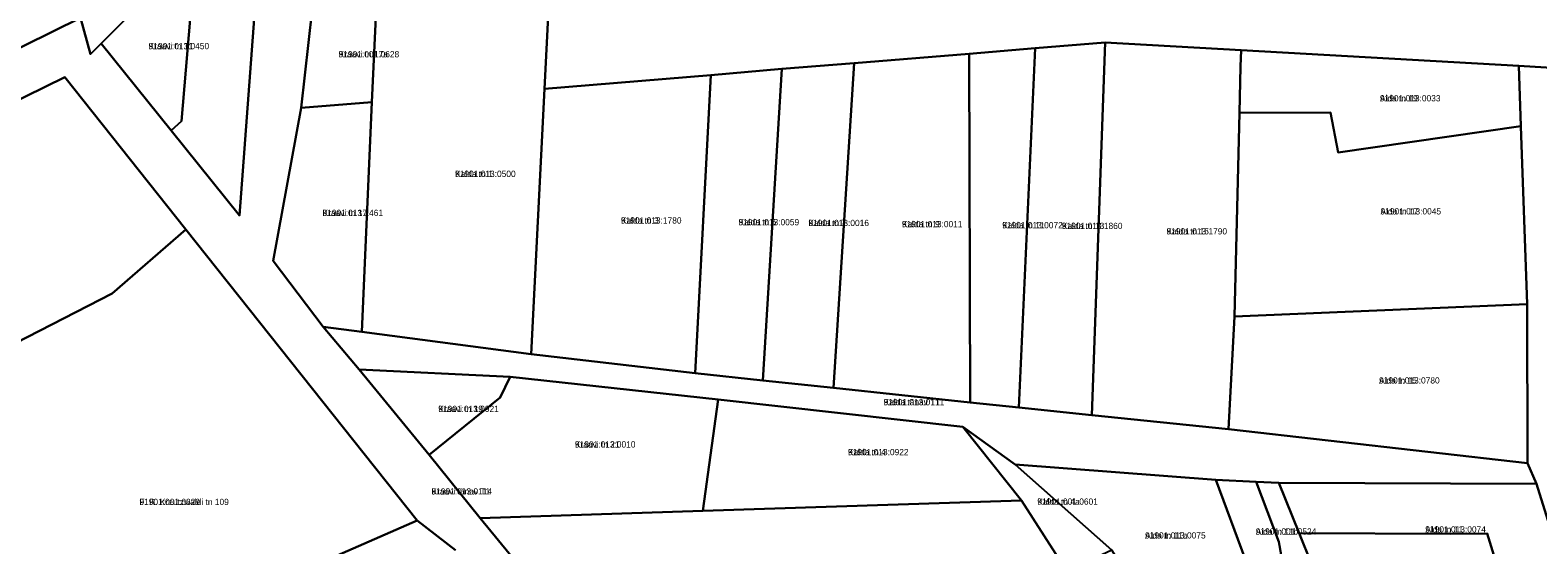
# Model space of a CAD drawing. Extents: x 675810 to 681273, y 6411190 to 6417565.
# Drawn here: x 678840.3 to 679201.2, y 6413785.2 to 6413908.4 of the extents above; entities that cross this region are included whole.
import ezdxf

# ---------------------------------------------------------------- set-up
doc = ezdxf.new("R2010")
doc.units = 0
for name, color, linetype in [('L_AADRESS', 7, 'Continuous'), ('PIIR', 7, 'Continuous'), ('TUNNUS', 7, 'Continuous')]:
    doc.layers.add(name, color=color, linetype=linetype)

msp = doc.modelspace()

# ---------------------------------------------------------------- linework, layer by layer
at = {"layer": 'PIIR'}
for points in [[(678908.02, 6414098.64), (678905.31, 6414062.9), (678901.04, 6414006.32), (678890.42, 6413864.01), (678874.02, 6413884.38), (678876.54, 6413886.59), (678880.01, 6413927.96), (678884.88, 6414004.33), (678890.93, 6414099.14)], [(678748.9, 6414045.88), (678773.05, 6414017.73), (678797.56, 6413987.81), (678798.11, 6413983.87), (678826.63, 6413946.46), (678833.98, 6413936.39), (678852.34, 6413911.31), (678771.22, 6413871.29)], [(678854.75, 6413902.61), (678852.34, 6413911.31), (678854.22, 6413934.74), (678880.01, 6413927.96), (678857.28, 6413905.17)], [(678876.54, 6413886.59), (678874.02, 6413884.38), (678857.28, 6413905.17), (678880.01, 6413927.96)], [(678922.11, 6413891.12), (678905.19, 6413889.77), (678907.83, 6413913.25), (678923.09, 6413913.22)], [(678964.34, 6413913.29), (678963.4, 6413894.33), (678960.22, 6413830.83), (678919.67, 6413836.19), (678922.11, 6413891.12), (678923.09, 6413913.22)], [(679097.63, 6413905.42), (679094.46, 6413816.24), (679076.93, 6413818.09), (679080.9, 6413904.04)], [(679097.63, 6413905.42), (679130.16, 6413903.57), (679130.06, 6413899.65), (679129.79, 6413888.58), (679128.56, 6413839.85), (679127.14, 6413812.87), (679094.46, 6413816.24)], [(679037.52, 6413900.45), (679065.06, 6413902.73), (679065.35, 6413819.31), (679032.62, 6413822.76)], [(679065.06, 6413902.73), (679080.9, 6413904.04), (679076.93, 6413818.09), (679065.35, 6413819.31)], [(679130.16, 6413903.57), (679196.66, 6413899.8), (679197.16, 6413885.36), (679153.42, 6413879.07), (679151.6, 6413888.68), (679129.79, 6413888.58), (679130.06, 6413899.65)], [(679003.23, 6413897.62), (679020.27, 6413899.08), (679015.65, 6413824.55), (678999.48, 6413826.27)], [(679020.27, 6413899.08), (679037.52, 6413900.45), (679032.62, 6413822.76), (679015.65, 6413824.55)], [(679196.66, 6413899.8), (679205.84, 6413899.28), (679207.5, 6413851.58), (679205.9, 6413842.68), (679206.48, 6413804.54), (679216.05, 6413792.01), (679231.04, 6413746.94), (679239.56, 6413721.03), (679241.97, 6413713.76), (679252.97, 6413680.43), (679249.07, 6413679.21), (679271.23, 6413613.71), (679259.28, 6413612.63), (679249.72, 6413644.17), (679243.75, 6413664.08), (679235.52, 6413689.16), (679223.07, 6413730.04), (679217.3, 6413749.31), (679212.4, 6413765.71), (679207.07, 6413779.92), (679200.86, 6413799.83), (679198.73, 6413804.8), (679198.65, 6413842.84), (679197.16, 6413885.36)], [(678795.17, 6413816.56), (678772.52, 6413859.76), (678848.62, 6413897.12), (678877.6, 6413860.64), (678859.96, 6413845.39), (678828, 6413829.05)], [(679003.23, 6413897.62), (678999.48, 6413826.27), (678960.22, 6413830.83), (678963.4, 6413894.33)], [(678922.11, 6413891.12), (678919.67, 6413836.19), (678910.44, 6413837.41), (678898.43, 6413853.15), (678905.19, 6413889.77)], [(679129.79, 6413888.58), (679151.6, 6413888.68), (679153.42, 6413879.07), (679197.16, 6413885.36), (679198.65, 6413842.84), (679128.56, 6413839.85)], [(678826.29, 6413728.84), (678795.17, 6413816.56), (678828, 6413829.05), (678859.96, 6413845.39), (678877.6, 6413860.64), (678932.91, 6413791.06), (678862.71, 6413760.35)], [(679127.14, 6413812.87), (679128.56, 6413839.85), (679198.65, 6413842.84), (679198.73, 6413804.8)], [(678910.44, 6413837.41), (678919.67, 6413836.19), (678960.22, 6413830.83), (678999.48, 6413826.27), (679015.65, 6413824.55), (679032.62, 6413822.76), (679065.35, 6413819.31), (679076.93, 6413818.09), (679094.46, 6413816.24), (679127.14, 6413812.87), (679198.73, 6413804.8), (679200.86, 6413799.83), (679139.17, 6413800.08), (679133.81, 6413800.32), (679124.13, 6413800.75), (679076.05, 6413804.42), (679063.55, 6413813.47), (679005.02, 6413819.99), (678955.23, 6413825.41), (678919.09, 6413827.21)], [(678919.09, 6413827.21), (678955.23, 6413825.41), (678952.79, 6413820.45), (678935.84, 6413806.79)], [(679005.02, 6413819.99), (679001.31, 6413793.35), (678948, 6413791.61), (678935.84, 6413806.79), (678952.79, 6413820.45), (678955.23, 6413825.41)], [(679005.02, 6413819.99), (679063.55, 6413813.47), (679077.61, 6413795.82), (679001.31, 6413793.35)], [(679063.55, 6413813.47), (679076.05, 6413804.42), (679099.24, 6413783.96), (679088.47, 6413778.92), (679077.61, 6413795.82)], [(679076.05, 6413804.42), (679124.13, 6413800.75), (679138.31, 6413762.5), (679116.06, 6413757.41), (679099.24, 6413783.96)], [(679124.13, 6413800.75), (679133.81, 6413800.32), (679139.23, 6413785.98), (679143.23, 6413763.68), (679138.31, 6413762.5)], [(679139.17, 6413800.08), (679144.1, 6413788.04), (679152.9, 6413765.99), (679143.23, 6413763.68), (679139.23, 6413785.98), (679133.81, 6413800.32)], [(679139.17, 6413800.08), (679200.86, 6413799.83), (679207.07, 6413779.92), (679192.67, 6413776.28), (679189.1, 6413787.94), (679180.37, 6413787.89), (679144.1, 6413788.04)], [(678948, 6413791.61), (679001.31, 6413793.35), (679077.61, 6413795.82), (679088.47, 6413778.92), (679049.95, 6413767.16), (678986.06, 6413749.64), (678983.09, 6413748.82)], [(679144.1, 6413788.04), (679180.37, 6413787.89), (679189.1, 6413787.94), (679192.67, 6413776.28), (679186.28, 6413774.66), (679152.9, 6413765.99)]]:
    msp.add_lwpolyline(points, close=True, dxfattribs=at)
for points in [[(678771.22, 6413871.29), (678852.34, 6413911.31), (678854.75, 6413902.61), (678857.28, 6413905.17), (678874.02, 6413884.38), (678890.42, 6413864.01), (678901.04, 6414006.32)], [(678907.83, 6413913.25), (678905.19, 6413889.77), (678898.43, 6413853.15), (678910.44, 6413837.41), (678919.09, 6413827.21), (678935.84, 6413806.79), (678948, 6413791.61), (678983.09, 6413748.82)], [(679421.76, 6413888.24), (679335.58, 6413893.31), (679300.66, 6413902.45), (679247.15, 6413899.15), (679205.84, 6413899.28), (679196.66, 6413899.8), (679130.16, 6413903.57), (679097.63, 6413905.42), (679080.9, 6413904.04), (679065.06, 6413902.73), (679037.52, 6413900.45), (679020.27, 6413899.08), (679003.23, 6413897.62), (678963.4, 6413894.33), (678964.34, 6413913.29)], [(678942.15, 6413783.91), (678932.91, 6413791.06), (678877.6, 6413860.64), (678848.62, 6413897.12), (678772.52, 6413859.76)], [(678862.71, 6413760.35), (678932.91, 6413791.06), (678942.15, 6413783.91)]]:
    msp.add_lwpolyline(points, dxfattribs=at)

# ---------------------------------------------------------------- texts
at = {"layer": 'L_AADRESS'}
for s, p in [('Kraavi tn 11', (678868.64, 6413903.81)), ('Kraavi tn 17a', (678914.14, 6413901.86)), ('Aida tn 19', (679163.41, 6413891.32)), ('Kalda tn 1', (678942.01, 6413873.24)), ('Kraavi tn 17', (678910.27, 6413863.9)), ('Aida tn 17', (679163.54, 6413864.27)), ('Kalda tn 3', (678981.72, 6413862.09)), ('Kalda tn 5', (679009.88, 6413861.68)), ('Kalda tn 7', (679026.59, 6413861.49)), ('Kalda tn 9', (679048.98, 6413861.22)), ('Kalda tn 11', (679072.98, 6413860.95)), ('Kalda tn 13', (679087.28, 6413860.78)), ('Kalda tn 15', (679112.31, 6413859.49)), ('Aida tn 15', (679163.2, 6413823.82)), ('Kraavi tn 19', (678937.99, 6413817)), ('Kalda tänav T1', (679044.61, 6413818.62)), ('Kraavi tn 21', (678970.7, 6413808.51)), ('Kalda tn 4', (679036.07, 6413806.67)), ('Kraavi tänav T1', (678936.36, 6413797.27)), ('F. R. Kreutzwaldi tn 109', (678866.45, 6413794.74)), ('Kalda tn 4a', (679081.39, 6413794.82)), ('Aida tn 11', (679174.27, 6413788.18)), ('Aida tn 11a', (679107.18, 6413786.74)), ('Aida tn 11b', (679133.68, 6413787.66))]:
    msp.add_text(s, height=1.5, dxfattribs=at).set_placement(p)
at = {"layer": 'TUNNUS'}
for s, p in [('91901:013:0450', (678868.64, 6413903.81)), ('91901:001:0628', (678914.14, 6413901.86)), ('91901:013:0033', (679163.41, 6413891.32)), ('91901:013:0500', (678942.01, 6413873.24)), ('91901:013:0045', (679163.54, 6413864.27)), ('91901:013:1461', (678910.27, 6413863.9)), ('91901:013:1780', (678981.72, 6413862.09)), ('91901:013:0059', (679009.88, 6413861.68)), ('91901:013:0016', (679026.59, 6413861.49)), ('91901:013:0011', (679048.98, 6413861.22)), ('91901:013:0072', (679072.98, 6413860.95)), ('91901:013:1860', (679087.28, 6413860.78)), ('91901:013:1790', (679112.31, 6413859.49)), ('91901:013:0780', (679163.2, 6413823.82)), ('91901:013:0111', (679044.61, 6413818.62)), ('91901:013:0921', (678937.99, 6413817)), ('91901:013:0010', (678970.7, 6413808.51)), ('91901:013:0922', (679036.07, 6413806.67)), ('91901:013:0114', (678936.36, 6413797.27)), ('91901:001:0329', (678866.45, 6413794.74)), ('91901:001:0601', (679081.39, 6413794.82)), ('91901:013:0074', (679174.27, 6413788.18)), ('91901:013:0075', (679107.18, 6413786.74)), ('91901:001:0524', (679133.68, 6413787.66))]:
    msp.add_text(s, height=1.5, dxfattribs=at).set_placement(p)

doc.saveas('drawing.dxf')
